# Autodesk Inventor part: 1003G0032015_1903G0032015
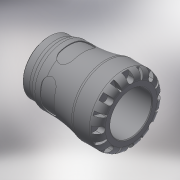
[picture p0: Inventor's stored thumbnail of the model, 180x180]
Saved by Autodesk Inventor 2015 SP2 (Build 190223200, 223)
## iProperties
Created: 2016-12
Part Number: 1003G0032015_1903G0032015
Material: Generic
Description: PLASSON FEMALE ADAPTOR 32x1 1/2" SERIES 1
Document SubType Name: Modeling
Designer: KIM
Mass: 142.338 g
Surface Area: 334.331 cm^2
Volume: 142.338 cm^3
Density: 1 g/cm^3
Appearance: Default
Author: KIM
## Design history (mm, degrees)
derived "1003G.ipt"
feature "Solid1::1003G.ipt"
tag "TaggingFeature1"
body "Solid1"
other parameters: "d0" = 95, "d1" = 28.14, "d2" = 32, "d4" = 64, "d6" = 67, "d8" = 54.4, "d13" = 9.6, "d14" = 9.6, "d15" = 0, "d17" = 360 deg, "d19" = 8 deg, "d20" = 0.64, "d21" = 0.64, "d22" = 8 deg, "d24" = 0, "d26" = 360 deg, "d32" = 6.4, "d33" = 6.4, "d39" = 1.34535, "d42" = 44.845, "d43" = 49.92, "d46" = 2.66667, "d47" = 19, "d48" = 42.60275, "d50" = 2.97, "d51" = 0.64, "d54" = 11.2, "d55" = 7.04, "d57" = 18.816, "d58" = 0, "d68" = 360 deg, "d72" = 0.64, "d74" = 0, "d76" = 9.52, "d_" = 32, "E_" = 64, "H_" = 95, "l_" = 67, "G_" = 44.845, "l_2" = 19, "d9" = 12, "d11" = 64, "d49" = 9
